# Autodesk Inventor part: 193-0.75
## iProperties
Created: 2007-06
Part Number: 193-0.75
Document SubType Name: Modeling
Designer: btaylor
Density: 1 g/cm^3
Author: btaylor
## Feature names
1. Sweep1
2. Extrusion1
3. Extrusion2
4. Fillet1
5. Fillet2
6. Extrusion3
7. Extrusion4
8. Sweep2
9. Fillet3
10. Fillet4
11. Chamfer1
12. Chamfer2
